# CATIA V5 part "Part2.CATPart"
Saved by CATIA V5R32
Part number: Part2
Bounding box of the stored display mesh (mm): x -15 to 15, y -15 to 15, z 0 to 20
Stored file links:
  D:\PROJECTS\Project 2022\CATIA V5 6R 2022\Resources\Part Files\c16_catia_v5_6r2022_prt\Roll Curve Joint-(Fig16-43)\Part2.CATPart
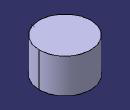
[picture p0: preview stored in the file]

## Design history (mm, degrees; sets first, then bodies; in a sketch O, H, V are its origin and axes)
Body1 (main body)
  Sketch1 on xy-plane, origin (0, 0, 0), H (1, 0, 0), V (0, 1, 0)
    circle A1 centre (0, 0) radius 15
    radius A1 = 15
  Pad1: profile Sketch1, direction (0, 0, 1), length 20
  Point1: type OnCurve, Support edge [face of Pad1 from Sketch1.A1 | end face of Pad1], RefPoint {extremum Reference edge [face of Pad1 from Sketch1.A1 | end face of Pad1], Direction (1, 2, 3)}, Length 58.791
